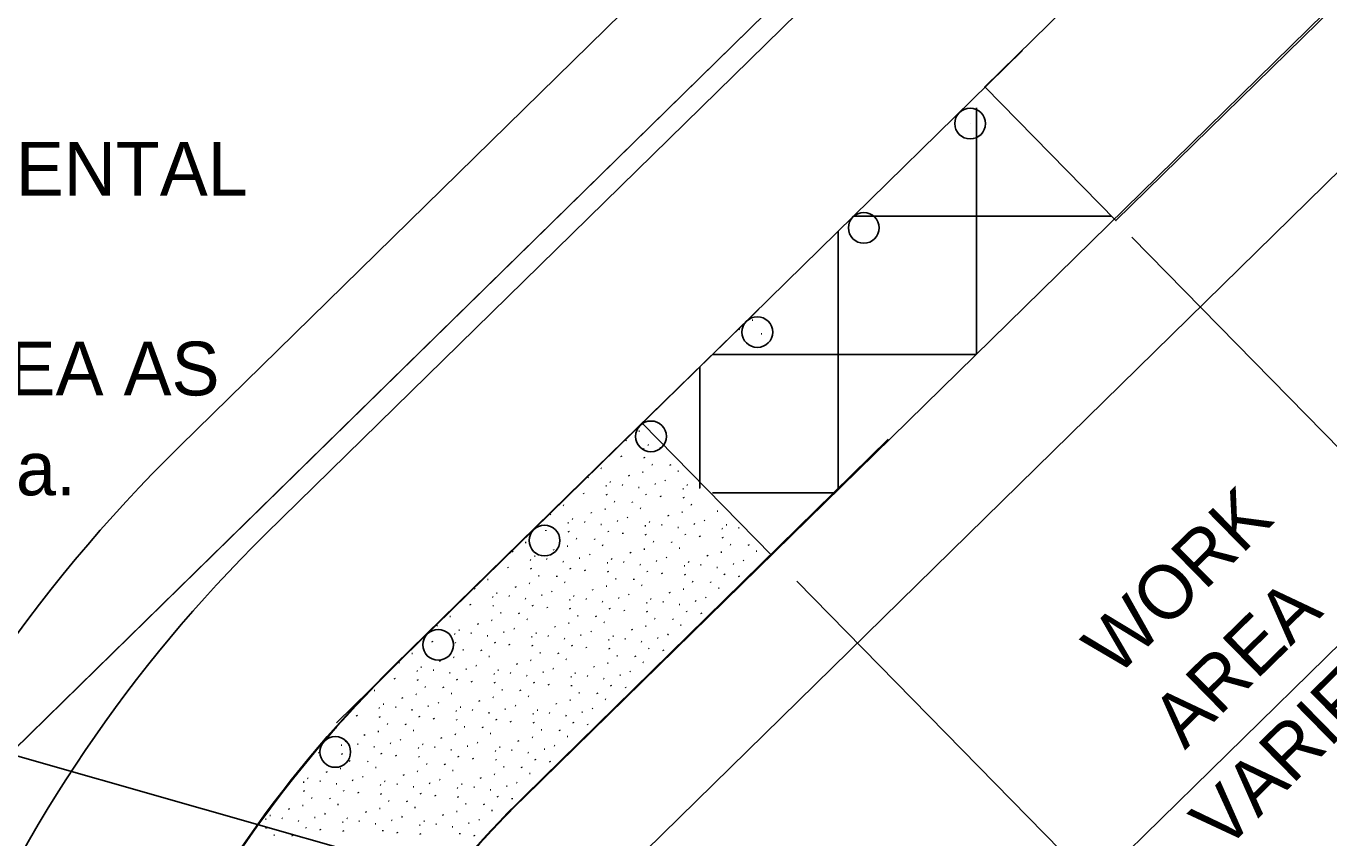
# Model space of a CAD drawing. Extents: x 16735 to 19510, y 5880 to 6929.
# Drawn here: x 16877.8 to 17047.4, y 6449.1 to 6554.7 of the extents above; entities that cross this region are included whole.
import ezdxf

# ---------------------------------------------------------------- set-up
doc = ezdxf.new("R2010")
doc.units = 0
for name, color, linetype in [('ALI_LEGAL_EX', 7, 'Continuous'), ('BORDER', 7, 'Continuous'), ('SCRATCH_LEVEL_A', 7, 'Continuous'), ('TRAFFIC_SIGNS_PR', 7, 'Continuous')]:
    doc.layers.add(name, color=color, linetype=linetype)

msp = doc.modelspace()

# ---------------------------------------------------------------- linework, layer by layer
at = {"layer": 'ALI_LEGAL_EX'}
msp.add_line((16866.49, 6450.99), (17215.7, 6793.27), dxfattribs=at)
at = {"layer": 'BORDER'}
for p, q in [((16897.83, 6500.06), (17318.59, 6912.48)), ((17329.79, 6901.05), (16909.03, 6488.64)), ((17363.39, 6866.77), (16942.75, 6454.47)), ((17374.59, 6855.35), (16953.19, 6442.3)), ((16867.78, 6452.26), (17214.45, 6792.05)), ((17007.49, 6551.55), (16950.32, 6495.51)), ((17000.67, 6542.05), (17000.67, 6542.05)), ((16973.17, 6517.91), (16925.83, 6471.5)), ((16973.17, 6517.91), (16950.27, 6495.56)), ((16970.61, 6515.3), (16970.7, 6515.23)), ((16972.3, 6516.48), (16972.39, 6516.46)), ((16973.48, 6514.69), (16973.57, 6514.68)), ((16957.54, 6502.02), (16957.64, 6502)), ((16989.97, 6500.76), (16942.63, 6454.36)), ((16942.69, 6454.53), (16990, 6500.99)), ((16955.85, 6500.84), (16955.94, 6500.77)), ((16958.72, 6500.23), (16958.81, 6500.21)), ((16955.32, 6498.67), (16955.28, 6498.79)), ((16958.17, 6499.74), (16958.27, 6499.72)), ((16958.3, 6498.52), (16958.26, 6498.64)), ((16960.31, 6499.85), (16960.4, 6499.84)), ((16952.63, 6497.2), (16952.72, 6497.18)), ((16958.05, 6496.7), (16958.14, 6496.68)), ((16959.24, 6497.67), (16959.34, 6497.65)), ((16961.67, 6497.54), (16961.62, 6497.66)), ((16962.64, 6496.81), (16962.73, 6496.8)), ((16950.27, 6495.56), (16925.77, 6471.55)), ((16950.94, 6496.02), (16951.03, 6495.95)), ((16953.26, 6494.92), (16953.35, 6494.9)), ((16953.8, 6495.41), (16953.89, 6495.39)), ((16955.39, 6495.03), (16955.48, 6495.01)), ((16956.32, 6496.16), (16956.27, 6496.28)), ((16959.63, 6495.15), (16959.73, 6495.13)), ((16960.95, 6495.64), (16961.04, 6495.56)), ((16963.82, 6495.03), (16963.91, 6495.01)), ((16950.4, 6493.85), (16950.36, 6493.97)), ((16953.38, 6493.7), (16953.34, 6493.81)), ((16957.52, 6494.69), (16957.61, 6494.67)), ((16958.53, 6493.72), (16958.48, 6493.84)), ((16960.42, 6493.47), (16960.38, 6493.59)), ((16963.27, 6494.53), (16963.37, 6494.51)), ((16963.4, 6493.31), (16963.36, 6493.43)), ((16965.41, 6494.65), (16965.5, 6494.63)), ((16947.71, 6492.38), (16947.8, 6492.36)), ((16951.4, 6491.33), (16951.35, 6491.45)), ((16953.13, 6491.88), (16953.23, 6491.86)), ((16954.33, 6492.85), (16954.42, 6492.83)), ((16956.75, 6492.72), (16956.71, 6492.84)), ((16957.72, 6491.99), (16957.82, 6491.97)), ((16963.15, 6491.49), (16963.24, 6491.47)), ((16964.34, 6492.47), (16964.44, 6492.45)), ((16967.74, 6491.61), (16967.83, 6491.59)), ((16946.02, 6491.2), (16946.11, 6491.13)), ((16948.34, 6490.09), (16948.43, 6490.08)), ((16948.88, 6490.59), (16948.98, 6490.57)), ((16950.47, 6490.21), (16950.56, 6490.19)), ((16952.6, 6489.87), (16952.69, 6489.85)), ((16954.72, 6490.33), (16954.81, 6490.31)), ((16956.03, 6490.82), (16956.13, 6490.74)), ((16958.9, 6490.21), (16958.99, 6490.19)), ((16960.49, 6489.83), (16960.58, 6489.81)), ((16961.42, 6490.95), (16961.37, 6491.07)), ((16964.73, 6489.95), (16964.83, 6489.93)), ((16966.05, 6490.44), (16966.14, 6490.36)), ((16968.92, 6489.83), (16969.01, 6489.81)), ((16945.48, 6489.03), (16945.44, 6489.15)), ((16948.46, 6488.87), (16948.42, 6488.99)), ((16953.61, 6488.9), (16953.56, 6489.01)), ((16955.5, 6488.65), (16955.46, 6488.77)), ((16958.35, 6489.71), (16958.45, 6489.69)), ((16958.48, 6488.49), (16958.44, 6488.61)), ((16962.62, 6489.48), (16962.71, 6489.46)), ((16963.63, 6488.51), (16963.58, 6488.63)), ((16965.52, 6488.27), (16965.47, 6488.39)), ((16968.37, 6489.33), (16968.46, 6489.31)), ((16968.5, 6488.11), (16968.45, 6488.23)), ((16970.51, 6489.45), (16970.6, 6489.43)), ((16941.1, 6486.38), (16941.19, 6486.3)), ((16942.79, 6487.55), (16942.88, 6487.53)), ((16946.48, 6486.51), (16946.44, 6486.63)), ((16948.22, 6487.05), (16948.31, 6487.04)), ((16949.41, 6488.03), (16949.5, 6488.01)), ((16951.83, 6487.9), (16951.79, 6488.02)), ((16952.81, 6487.17), (16952.9, 6487.15)), ((16958.23, 6486.67), (16958.33, 6486.65)), ((16959.42, 6487.64), (16959.52, 6487.62)), ((16961.85, 6487.52), (16961.8, 6487.63)), ((16962.82, 6486.79), (16962.91, 6486.77)), ((16969.44, 6487.26), (16969.53, 6487.24)), ((16971.87, 6487.13), (16971.82, 6487.25)), ((16972.84, 6486.41), (16972.93, 6486.39)), ((16943.42, 6485.27), (16943.51, 6485.25)), ((16943.97, 6485.77), (16944.06, 6485.75)), ((16945.55, 6485.39), (16945.64, 6485.37)), ((16947.68, 6485.04), (16947.77, 6485.03)), ((16949.8, 6485.51), (16949.89, 6485.49)), ((16951.12, 6486), (16951.21, 6485.92)), ((16953.44, 6484.89), (16953.53, 6484.87)), ((16953.98, 6485.39), (16954.07, 6485.37)), ((16955.57, 6485.01), (16955.66, 6484.99)), ((16956.5, 6486.13), (16956.45, 6486.25)), ((16957.7, 6484.66), (16957.79, 6484.64)), ((16959.81, 6485.13), (16959.91, 6485.11)), ((16961.13, 6485.62), (16961.22, 6485.54)), ((16964, 6485.01), (16964.09, 6484.99)), ((16966.52, 6485.75), (16966.47, 6485.87)), ((16968.25, 6486.29), (16968.34, 6486.27)), ((16969.83, 6484.75), (16969.92, 6484.73)), ((16971.15, 6485.23), (16971.24, 6485.16)), ((16940.56, 6484.21), (16940.52, 6484.33)), ((16943.54, 6484.05), (16943.5, 6484.17)), ((16944.49, 6483.2), (16944.58, 6483.19)), ((16946.91, 6483.08), (16946.87, 6483.2)), ((16948.69, 6484.07), (16948.64, 6484.19)), ((16950.58, 6483.83), (16950.54, 6483.95)), ((16953.56, 6483.67), (16953.52, 6483.79)), ((16958.71, 6483.69), (16958.66, 6483.81)), ((16960.6, 6483.44), (16960.56, 6483.56)), ((16963.45, 6484.51), (16963.55, 6484.49)), ((16963.58, 6483.29), (16963.54, 6483.41)), ((16965.59, 6484.63), (16965.68, 6484.61)), ((16967.71, 6484.28), (16967.81, 6484.26)), ((16968.73, 6483.31), (16968.68, 6483.43)), ((16970.62, 6483.06), (16970.57, 6483.18)), ((16936.18, 6481.56), (16936.27, 6481.48)), ((16937.87, 6482.73), (16937.96, 6482.71)), ((16941.56, 6481.69), (16941.52, 6481.81)), ((16943.3, 6482.23), (16943.39, 6482.21)), ((16947.89, 6482.35), (16947.98, 6482.33)), ((16951.58, 6481.31), (16951.53, 6481.43)), ((16953.31, 6481.85), (16953.41, 6481.83)), ((16954.51, 6482.82), (16954.6, 6482.8)), ((16956.93, 6482.69), (16956.89, 6482.81)), ((16957.9, 6481.97), (16958, 6481.95)), ((16963.33, 6481.47), (16963.42, 6481.45)), ((16964.52, 6482.44), (16964.62, 6482.42)), ((16966.95, 6482.31), (16966.9, 6482.43)), ((16967.92, 6481.59), (16968.01, 6481.57)), ((16938.5, 6480.45), (16938.59, 6480.43)), ((16939.05, 6480.95), (16939.14, 6480.93)), ((16940.63, 6480.57), (16940.72, 6480.55)), ((16942.76, 6480.22), (16942.85, 6480.2)), ((16944.88, 6480.69), (16944.97, 6480.67)), ((16946.2, 6481.18), (16946.29, 6481.1)), ((16948.52, 6480.07), (16948.61, 6480.05)), ((16949.06, 6480.57), (16949.16, 6480.55)), ((16950.65, 6480.19), (16950.74, 6480.17)), ((16952.78, 6479.84), (16952.87, 6479.82)), ((16954.9, 6480.31), (16954.99, 6480.29)), ((16956.21, 6480.79), (16956.31, 6480.72)), ((16958.54, 6479.69), (16958.63, 6479.67)), ((16959.08, 6480.18), (16959.17, 6480.16)), ((16960.67, 6479.81), (16960.76, 6479.79)), ((16961.6, 6480.93), (16961.55, 6481.05)), ((16964.91, 6479.93), (16965.01, 6479.91)), ((16966.23, 6480.41), (16966.32, 6480.34)), ((16932.95, 6477.91), (16933.04, 6477.89)), ((16935.65, 6479.39), (16935.6, 6479.51)), ((16938.63, 6479.23), (16938.58, 6479.35)), ((16939.57, 6478.38), (16939.66, 6478.36)), ((16941.99, 6478.26), (16941.95, 6478.37)), ((16943.77, 6479.25), (16943.73, 6479.37)), ((16945.66, 6479.01), (16945.62, 6479.13)), ((16948.64, 6478.85), (16948.6, 6478.97)), ((16949.59, 6478), (16949.68, 6477.98)), ((16952.01, 6477.87), (16951.97, 6477.99)), ((16953.79, 6478.87), (16953.74, 6478.99)), ((16955.68, 6478.62), (16955.64, 6478.74)), ((16958.66, 6478.47), (16958.62, 6478.59)), ((16962.8, 6479.46), (16962.89, 6479.44)), ((16963.81, 6478.49), (16963.76, 6478.61)), ((16965.7, 6478.24), (16965.65, 6478.36)), ((16931.26, 6476.74), (16931.35, 6476.66)), ((16936.64, 6476.87), (16936.6, 6476.99)), ((16938.38, 6477.41), (16938.47, 6477.39)), ((16941.28, 6476.35), (16941.37, 6476.28)), ((16942.97, 6477.53), (16943.06, 6477.51)), ((16946.66, 6476.49), (16946.62, 6476.61)), ((16948.4, 6477.03), (16948.49, 6477.01)), ((16952.99, 6477.15), (16953.08, 6477.13)), ((16956.68, 6476.11), (16956.63, 6476.23)), ((16958.41, 6476.65), (16958.51, 6476.63)), ((16959.6, 6477.62), (16959.7, 6477.6)), ((16962.03, 6477.49), (16961.98, 6477.61)), ((16963, 6476.77), (16963.09, 6476.75)), ((16930.73, 6474.57), (16930.68, 6474.69)), ((16933.58, 6475.63), (16933.67, 6475.61)), ((16933.71, 6474.41), (16933.66, 6474.53)), ((16934.13, 6476.13), (16934.22, 6476.11)), ((16935.71, 6475.75), (16935.8, 6475.73)), ((16937.84, 6475.4), (16937.93, 6475.38)), ((16938.85, 6474.43), (16938.81, 6474.55)), ((16939.96, 6475.87), (16940.05, 6475.85)), ((16943.6, 6475.25), (16943.69, 6475.23)), ((16944.15, 6475.74), (16944.24, 6475.73)), ((16945.73, 6475.37), (16945.82, 6475.35)), ((16947.86, 6475.02), (16947.95, 6475)), ((16949.98, 6475.49), (16950.07, 6475.47)), ((16951.3, 6475.97), (16951.39, 6475.9)), ((16953.62, 6474.87), (16953.71, 6474.85)), ((16954.16, 6475.36), (16954.25, 6475.34)), ((16955.75, 6474.99), (16955.84, 6474.97)), ((16957.88, 6474.64), (16957.97, 6474.62)), ((16959.99, 6475.11), (16960.09, 6475.09)), ((16961.31, 6475.59), (16961.4, 6475.52)), ((16928.03, 6473.09), (16928.12, 6473.07)), ((16934.65, 6473.56), (16934.74, 6473.54)), ((16937.07, 6473.43), (16937.03, 6473.55)), ((16940.74, 6474.18), (16940.7, 6474.3)), ((16943.72, 6474.03), (16943.68, 6474.15)), ((16944.67, 6473.18), (16944.76, 6473.16)), ((16947.09, 6473.05), (16947.05, 6473.17)), ((16948.87, 6474.05), (16948.83, 6474.17)), ((16950.76, 6473.8), (16950.72, 6473.92)), ((16953.74, 6473.65), (16953.7, 6473.77)), ((16954.69, 6472.8), (16954.78, 6472.78)), ((16957.11, 6472.67), (16957.07, 6472.79)), ((16958.89, 6473.67), (16958.84, 6473.79)), ((16960.78, 6473.42), (16960.74, 6473.54)), ((16926.34, 6471.92), (16926.43, 6471.84)), ((16929.21, 6471.31), (16929.3, 6471.29)), ((16931.72, 6472.05), (16931.68, 6472.17)), ((16933.46, 6472.59), (16933.55, 6472.57)), ((16936.36, 6471.53), (16936.45, 6471.46)), ((16938.05, 6472.71), (16938.14, 6472.69)), ((16941.74, 6471.67), (16941.7, 6471.79)), ((16943.48, 6472.21), (16943.57, 6472.19)), ((16946.38, 6471.15), (16946.47, 6471.08)), ((16948.07, 6472.33), (16948.16, 6472.31)), ((16951.76, 6471.29), (16951.71, 6471.41)), ((16953.5, 6471.83), (16953.59, 6471.81)), ((16958.08, 6471.95), (16958.18, 6471.93)), ((16925.81, 6469.75), (16925.76, 6469.86)), ((16928.66, 6470.81), (16928.75, 6470.79)), ((16928.79, 6469.59), (16928.74, 6469.71)), ((16930.79, 6470.93), (16930.89, 6470.91)), ((16932.92, 6470.58), (16933.01, 6470.56)), ((16933.93, 6469.61), (16933.89, 6469.73)), ((16935.04, 6471.05), (16935.13, 6471.03)), ((16935.83, 6469.36), (16935.78, 6469.48)), ((16938.68, 6470.43), (16938.77, 6470.41)), ((16939.23, 6470.92), (16939.32, 6470.9)), ((16940.81, 6470.55), (16940.9, 6470.53)), ((16942.94, 6470.2), (16943.03, 6470.18)), ((16945.06, 6470.67), (16945.15, 6470.65)), ((16948.7, 6470.05), (16948.79, 6470.03)), ((16949.24, 6470.54), (16949.34, 6470.52)), ((16950.83, 6470.16), (16950.92, 6470.15)), ((16952.96, 6469.82), (16953.05, 6469.8)), ((16955.08, 6470.28), (16955.17, 6470.27)), ((16956.39, 6470.77), (16956.49, 6470.7)), ((16923.11, 6468.27), (16923.2, 6468.25)), ((16928.54, 6467.77), (16928.63, 6467.75)), ((16929.73, 6468.74), (16929.82, 6468.72)), ((16932.16, 6468.61), (16932.11, 6468.73)), ((16933.13, 6467.89), (16933.22, 6467.87)), ((16938.81, 6469.21), (16938.76, 6469.33)), ((16939.75, 6468.36), (16939.84, 6468.34)), ((16942.17, 6468.23), (16942.13, 6468.35)), ((16943.95, 6469.23), (16943.91, 6469.35)), ((16945.84, 6468.98), (16945.8, 6469.1)), ((16948.82, 6468.83), (16948.78, 6468.95)), ((16949.77, 6467.98), (16949.86, 6467.96)), ((16952.19, 6467.85), (16952.15, 6467.97)), ((16953.97, 6468.85), (16953.92, 6468.97)), ((16955.86, 6468.6), (16955.82, 6468.72)), ((16921.46, 6467.07), (16921.51, 6467.02)), ((16924.29, 6466.48), (16924.38, 6466.47)), ((16925.88, 6466.11), (16925.97, 6466.09)), ((16926.8, 6467.23), (16926.76, 6467.35)), ((16930.12, 6466.23), (16930.21, 6466.21)), ((16931.44, 6466.71), (16931.53, 6466.64)), ((16934.31, 6466.1), (16934.4, 6466.08)), ((16936.82, 6466.85), (16936.78, 6466.97)), ((16938.56, 6467.39), (16938.65, 6467.37)), ((16941.46, 6466.33), (16941.55, 6466.26)), ((16943.15, 6467.51), (16943.24, 6467.49)), ((16946.84, 6466.47), (16946.8, 6466.59)), ((16948.58, 6467.01), (16948.67, 6466.99)), ((16953.17, 6467.12), (16953.26, 6467.11)), ((16920.89, 6464.92), (16920.84, 6465.04)), ((16923.74, 6465.99), (16923.83, 6465.97)), ((16923.87, 6464.77), (16923.82, 6464.89)), ((16928, 6465.76), (16928.09, 6465.74)), ((16929.01, 6464.79), (16928.97, 6464.91)), ((16930.91, 6464.54), (16930.86, 6464.66)), ((16933.76, 6465.61), (16933.85, 6465.59)), ((16933.89, 6464.39), (16933.84, 6464.51)), ((16935.89, 6465.73), (16935.98, 6465.71)), ((16938.02, 6465.38), (16938.11, 6465.36)), ((16939.03, 6464.41), (16938.99, 6464.53)), ((16940.14, 6465.85), (16940.23, 6465.83)), ((16943.78, 6465.23), (16943.87, 6465.21)), ((16944.33, 6465.72), (16944.42, 6465.7)), ((16945.91, 6465.34), (16946, 6465.32)), ((16948.04, 6465), (16948.13, 6464.98)), ((16950.16, 6465.46), (16950.25, 6465.44)), ((16951.48, 6465.95), (16951.57, 6465.88)), ((16918.19, 6463.45), (16918.28, 6463.43)), ((16923.62, 6462.95), (16923.71, 6462.93)), ((16924.81, 6463.92), (16924.9, 6463.9)), ((16927.24, 6463.79), (16927.19, 6463.91)), ((16928.21, 6463.07), (16928.3, 6463.05)), ((16934.83, 6463.54), (16934.92, 6463.52)), ((16937.25, 6463.41), (16937.21, 6463.53)), ((16938.23, 6462.69), (16938.32, 6462.67)), ((16940.92, 6464.16), (16940.88, 6464.28)), ((16943.9, 6464.01), (16943.86, 6464.13)), ((16944.85, 6463.16), (16944.94, 6463.14)), ((16947.27, 6463.03), (16947.23, 6463.15)), ((16949.05, 6464.03), (16949.01, 6464.15)), ((16950.94, 6463.78), (16950.9, 6463.9)), ((16918.82, 6461.17), (16918.91, 6461.15)), ((16919.37, 6461.66), (16919.46, 6461.64)), ((16920.96, 6461.29), (16921.05, 6461.27)), ((16921.89, 6462.41), (16921.84, 6462.53)), ((16923.08, 6460.94), (16923.18, 6460.92)), ((16925.2, 6461.41), (16925.29, 6461.39)), ((16926.52, 6461.89), (16926.61, 6461.82)), ((16929.39, 6461.28), (16929.48, 6461.26)), ((16931.9, 6462.03), (16931.86, 6462.15)), ((16933.64, 6462.57), (16933.73, 6462.55)), ((16935.22, 6461.02), (16935.31, 6461.01)), ((16936.54, 6461.51), (16936.63, 6461.44)), ((16941.92, 6461.65), (16941.88, 6461.76)), ((16943.66, 6462.19), (16943.75, 6462.17)), ((16946.56, 6461.13), (16946.65, 6461.05)), ((16948.25, 6462.3), (16948.34, 6462.28)), ((16915.97, 6460.1), (16915.92, 6460.22)), ((16918.95, 6459.95), (16918.9, 6460.07)), ((16924.09, 6459.97), (16924.05, 6460.09)), ((16925.99, 6459.72), (16925.94, 6459.84)), ((16928.84, 6460.79), (16928.93, 6460.77)), ((16928.97, 6459.57), (16928.92, 6459.69)), ((16930.97, 6460.9), (16931.07, 6460.89)), ((16933.1, 6460.56), (16933.19, 6460.54)), ((16934.11, 6459.59), (16934.07, 6459.71)), ((16936.01, 6459.34), (16935.96, 6459.46)), ((16938.86, 6460.41), (16938.95, 6460.39)), ((16938.99, 6459.18), (16938.94, 6459.3)), ((16939.41, 6460.9), (16939.5, 6460.88)), ((16940.99, 6460.52), (16941.08, 6460.5)), ((16943.12, 6460.18), (16943.21, 6460.16)), ((16944.13, 6459.21), (16944.09, 6459.33)), ((16945.24, 6460.64), (16945.33, 6460.62)), ((16916.97, 6457.59), (16916.92, 6457.71)), ((16918.7, 6458.13), (16918.79, 6458.11)), ((16919.89, 6459.1), (16919.98, 6459.08)), ((16922.32, 6458.97), (16922.27, 6459.09)), ((16923.29, 6458.25), (16923.38, 6458.23)), ((16928.72, 6457.75), (16928.81, 6457.73)), ((16929.91, 6458.72), (16930, 6458.7)), ((16932.34, 6458.59), (16932.29, 6458.71)), ((16933.31, 6457.86), (16933.4, 6457.85)), ((16939.93, 6458.34), (16940.02, 6458.32)), ((16942.35, 6458.21), (16942.31, 6458.33)), ((16946.02, 6458.96), (16945.98, 6459.08)), ((16913.9, 6456.35), (16914, 6456.33)), ((16914.45, 6456.84), (16914.54, 6456.82)), ((16916.04, 6456.47), (16916.13, 6456.45)), ((16918.17, 6456.12), (16918.26, 6456.1)), ((16920.28, 6456.59), (16920.37, 6456.57)), ((16921.6, 6457.07), (16921.69, 6457)), ((16923.92, 6455.97), (16924.01, 6455.95)), ((16924.47, 6456.46), (16924.56, 6456.44)), ((16926.06, 6456.08), (16926.15, 6456.06)), ((16926.98, 6457.21), (16926.94, 6457.33)), ((16930.3, 6456.2), (16930.39, 6456.18)), ((16931.62, 6456.69), (16931.71, 6456.62)), ((16934.49, 6456.08), (16934.58, 6456.06)), ((16937, 6456.82), (16936.96, 6456.94)), ((16938.74, 6457.37), (16938.83, 6457.35)), ((16941.64, 6456.31), (16941.73, 6456.23)), ((16943.33, 6457.48), (16943.42, 6457.46)), ((16914.03, 6455.13), (16913.99, 6455.25)), ((16914.97, 6454.28), (16915.07, 6454.26)), ((16917.4, 6454.15), (16917.35, 6454.27)), ((16919.18, 6455.15), (16919.13, 6455.27)), ((16921.07, 6454.9), (16921.02, 6455.02)), ((16924.05, 6454.75), (16924, 6454.87)), ((16928.18, 6455.74), (16928.27, 6455.72)), ((16929.19, 6454.77), (16929.15, 6454.89)), ((16931.09, 6454.52), (16931.04, 6454.64)), ((16933.94, 6455.58), (16934.03, 6455.56)), ((16934.07, 6454.36), (16934.02, 6454.48)), ((16936.07, 6455.7), (16936.16, 6455.68)), ((16938.2, 6455.36), (16938.29, 6455.34)), ((16939.21, 6454.39), (16939.17, 6454.5)), ((16940.32, 6455.82), (16940.41, 6455.8)), ((16941.1, 6454.14), (16941.06, 6454.26)), ((16912.05, 6452.77), (16912, 6452.89)), ((16913.78, 6453.31), (16913.87, 6453.29)), ((16918.37, 6453.43), (16918.46, 6453.41)), ((16922.07, 6452.39), (16922.02, 6452.5)), ((16923.8, 6452.93), (16923.89, 6452.91)), ((16924.99, 6453.9), (16925.08, 6453.88)), ((16927.42, 6453.77), (16927.37, 6453.89)), ((16928.39, 6453.04), (16928.48, 6453.02)), ((16933.82, 6452.54), (16933.91, 6452.53)), ((16935.01, 6453.52), (16935.1, 6453.5)), ((16937.43, 6453.39), (16937.39, 6453.51)), ((16938.41, 6452.66), (16938.5, 6452.64)), ((16908.99, 6451.53), (16909.08, 6451.51)), ((16909.53, 6452.02), (16909.62, 6452)), ((16911.12, 6451.64), (16911.21, 6451.63)), ((16913.25, 6451.3), (16913.34, 6451.28)), ((16915.36, 6451.76), (16915.46, 6451.74)), ((16916.68, 6452.25), (16916.77, 6452.18)), ((16919, 6451.14), (16919.09, 6451.13)), ((16919.55, 6451.64), (16919.64, 6451.62)), ((16921.14, 6451.26), (16921.23, 6451.24)), ((16923.26, 6450.92), (16923.36, 6450.9)), ((16925.38, 6451.38), (16925.47, 6451.36)), ((16926.7, 6451.87), (16926.79, 6451.79)), ((16929.02, 6450.76), (16929.11, 6450.74)), ((16929.57, 6451.26), (16929.66, 6451.24)), ((16931.15, 6450.88), (16931.25, 6450.86)), ((16932.08, 6452), (16932.04, 6452.12)), ((16935.4, 6451), (16935.49, 6450.98)), ((16936.72, 6451.49), (16936.81, 6451.41)), ((16909.11, 6450.31), (16909.07, 6450.43)), ((16910.06, 6449.46), (16910.15, 6449.44)), ((16912.48, 6449.33), (16912.44, 6449.45)), ((16914.26, 6450.33), (16914.21, 6450.45)), ((16916.15, 6450.08), (16916.11, 6450.2)), ((16919.13, 6449.92), (16919.08, 6450.04)), ((16924.27, 6449.95), (16924.23, 6450.07)), ((16926.17, 6449.7), (16926.12, 6449.82)), ((16929.15, 6449.54), (16929.1, 6449.66)), ((16933.28, 6450.53), (16933.37, 6450.52)), ((16934.29, 6449.56), (16934.25, 6449.68)), ((16936.19, 6449.32), (16936.14, 6449.44))]:
    msp.add_line(p, q, dxfattribs=at)
msp.add_lwpolyline([(17088.53, 6596.94), (17071.47, 6614.35), (17002.57, 6546.82), (17019.63, 6529.42)], close=True, dxfattribs=at)
for points in [[(16950.32, 6495.51), (17007.49, 6551.55)], [(16918.22, 6464.05), (16950.32, 6495.51)]]:
    msp.add_lwpolyline(points, dxfattribs=at)
for centre, radius, start, end in [((17037.83, 6357.23), 200, 134.4258, 179.9999), ((17037.83, 6357.23), 184, 134.4258, 180.0001), ((17037.77, 6357.29), 160, 134.4259, 175.8987), ((17037.83, 6357.23), 160, 134.4258, 175.8987), ((17037.83, 6357.23), 136, 134.3562, 180.0001), ((17037.77, 6357.29), 136, 134.3562, 175.8987), ((17037.83, 6357.23), 136, 134.4258, 175.1733)]:
    msp.add_arc(centre, radius, start, end, dxfattribs=at)
at = {"layer": 'SCRATCH_LEVEL_A'}
for centre in [(17000.67, 6542.05), (16986.83, 6528.48), (16972.98, 6514.91), (16959.14, 6501.34), (16945.29, 6487.78), (16931.45, 6474.21), (16918.06, 6460.27)]:
    msp.add_circle(centre, 2, dxfattribs=at)
at = {"layer": 'TRAFFIC_SIGNS_PR'}
for p, q in [((17001.49, 6512.05), (17001.49, 6544.09)), ((17019.06, 6530), (16985.52, 6530)), ((16983.49, 6494.6), (16983.49, 6528.01)), ((17064.92, 6483.21), (17021.73, 6527.27)), ((17001.44, 6512), (16967.15, 6512)), ((16965.49, 6494.6), (16965.49, 6510.37)), ((16958.01, 6503.04), (16974.81, 6485.9)), ((16983.07, 6494), (16967.15, 6494)), ((17061.42, 6486.78), (17031.97, 6457.92)), ((16978.13, 6482.51), (17020.31, 6439.48)), ((16953.87, 6437.75), (16836.92, 6471.08)), ((17031.97, 6457.92), (16996.48, 6423.13))]:
    msp.add_line(p, q, dxfattribs=at)

# ---------------------------------------------------------------- texts
at = {"layer": 'SCRATCH_LEVEL_A'}
for s, p in [('PLACE ADDITIONAL SUPPLEMENTAL', (16739.7, 6532.67)), ('THROUGHOUT THE WORK AREA AS', (16739.7, 6506.67)), ('DEPICTED ON TYPICAL M0090a.', (16739.7, 6493.67))]:
    msp.add_text(s, height=7, dxfattribs=at).set_placement(p)
at = {"layer": 'TRAFFIC_SIGNS_PR'}
for s, p in [('WORK', (17019.66, 6469.89)), ('AREA', (17028.61, 6460.45)), ('VARIES', (17033.67, 6447.21))]:
    msp.add_text(s, height=7, rotation=44.4259, dxfattribs=at).set_placement(p)

doc.saveas('drawing.dxf')
